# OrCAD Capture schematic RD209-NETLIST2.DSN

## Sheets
1 3: size A3
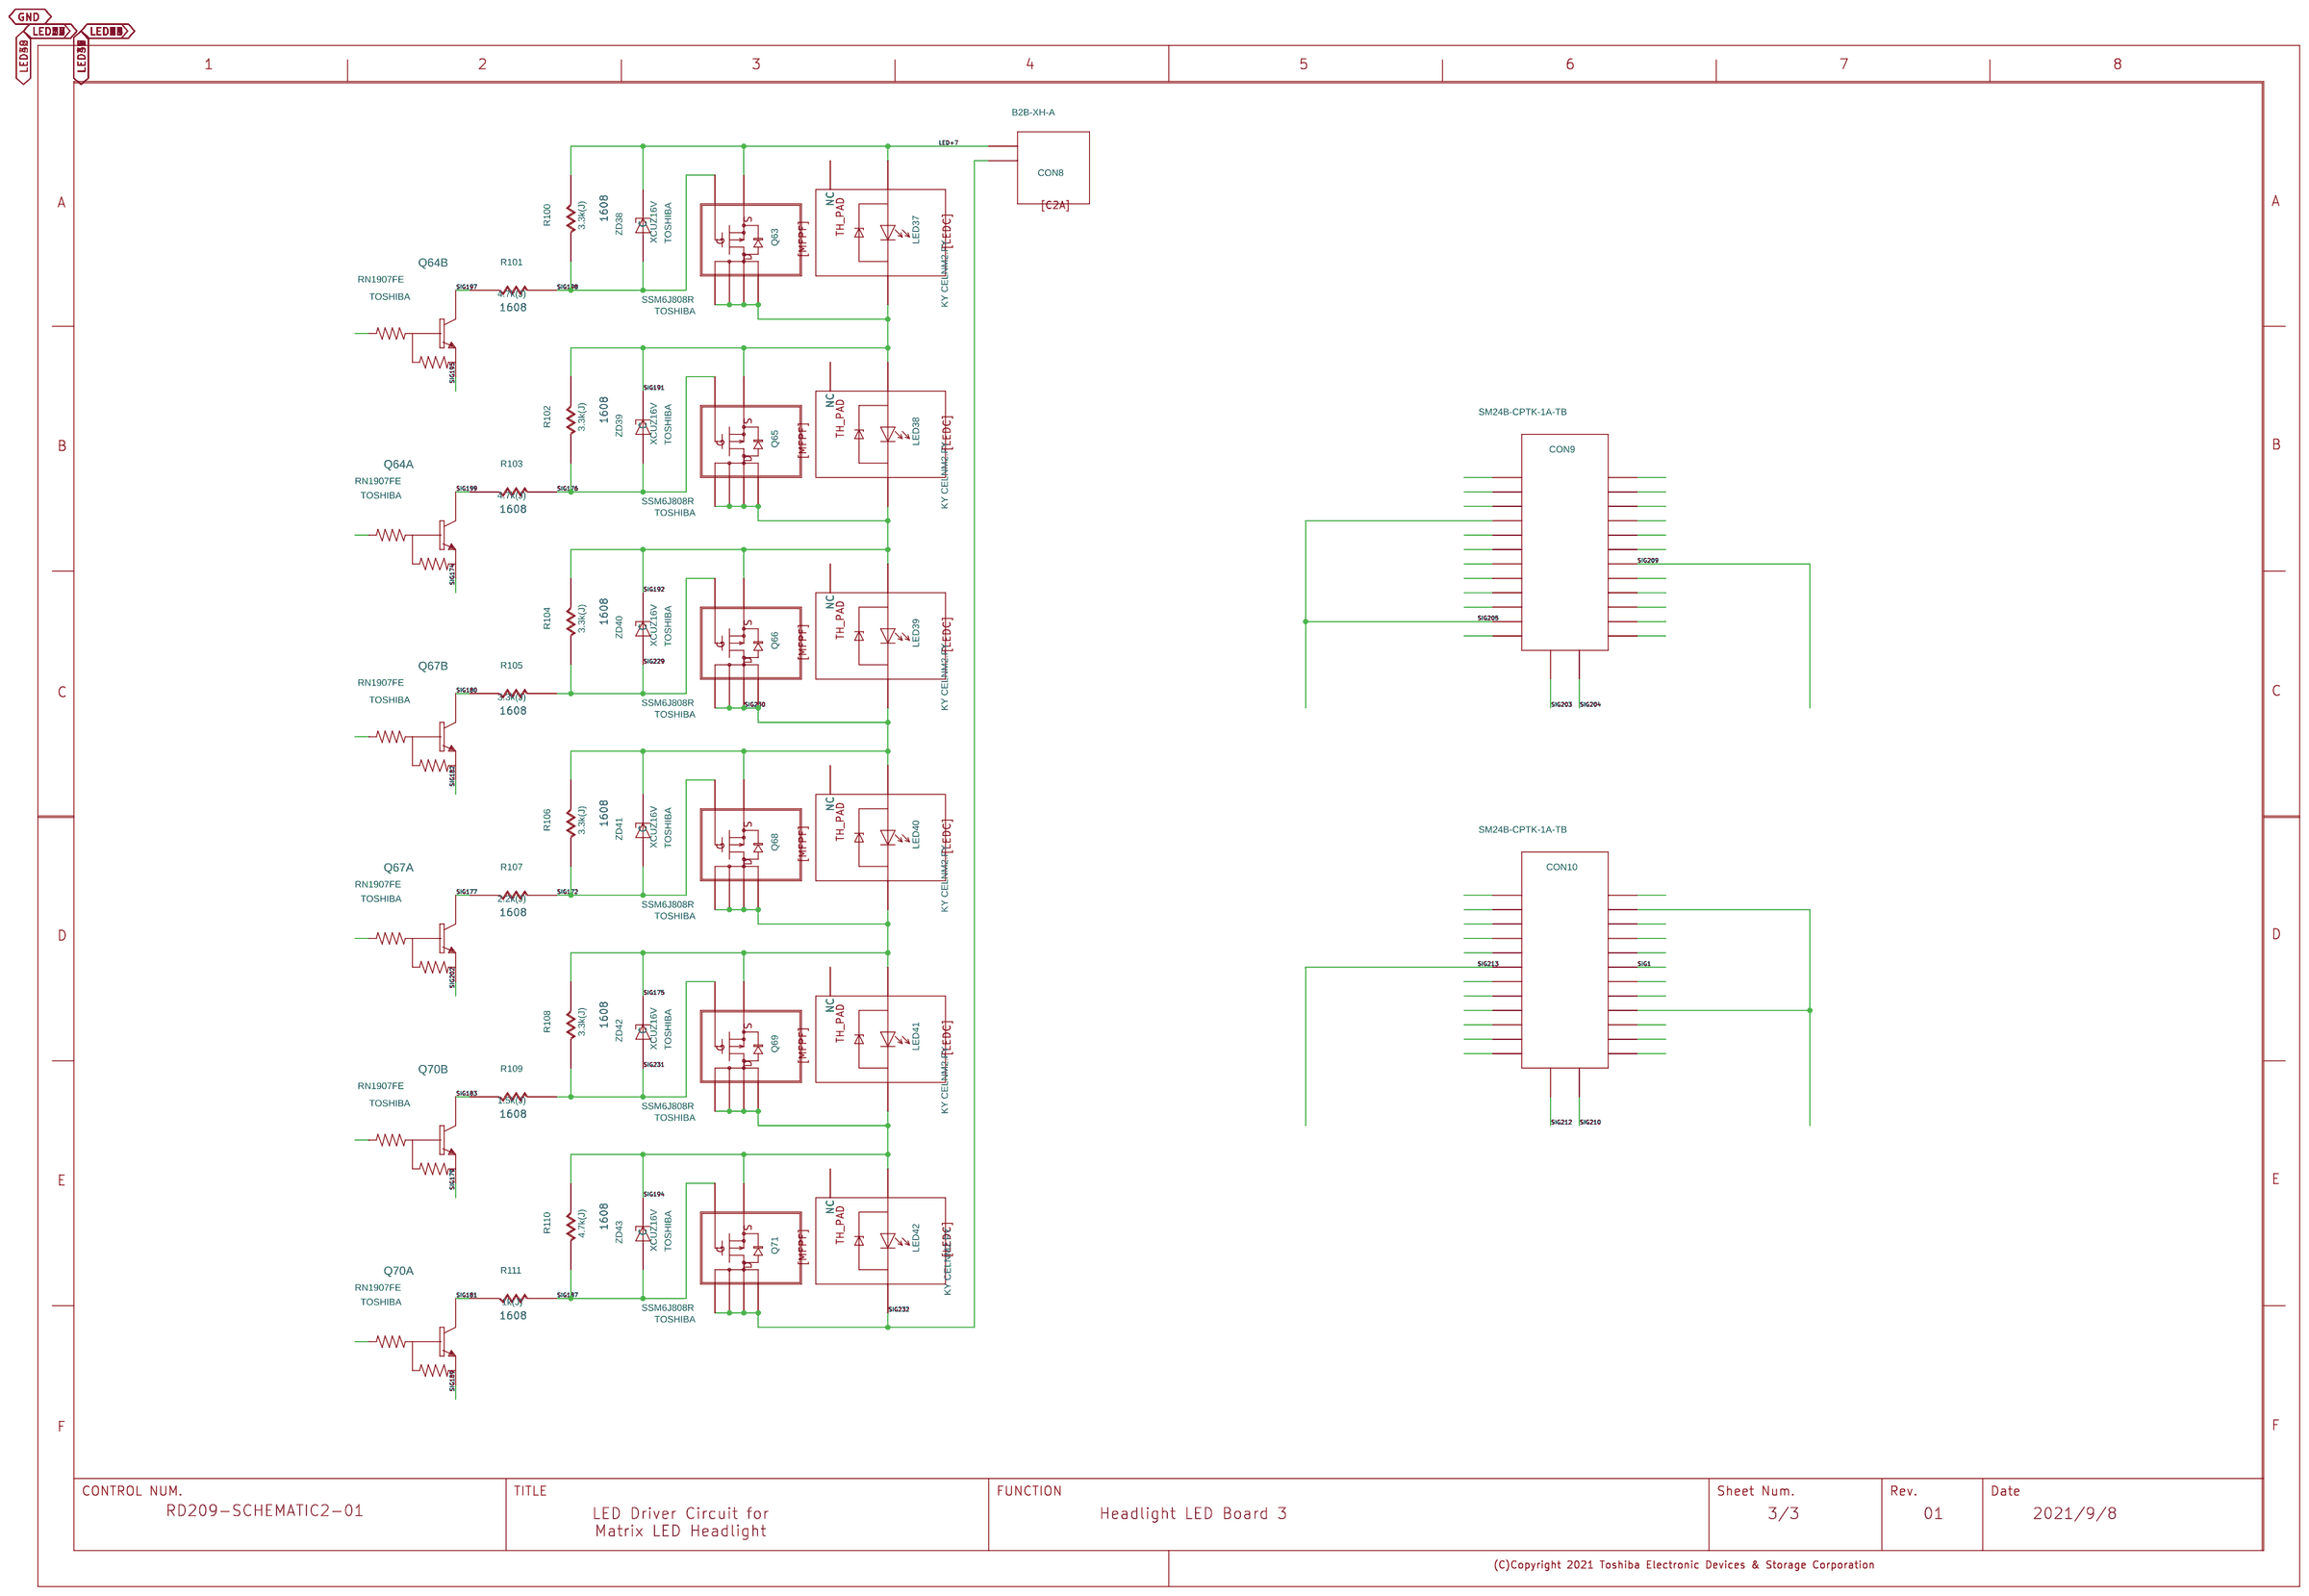
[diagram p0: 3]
2 2: size A3
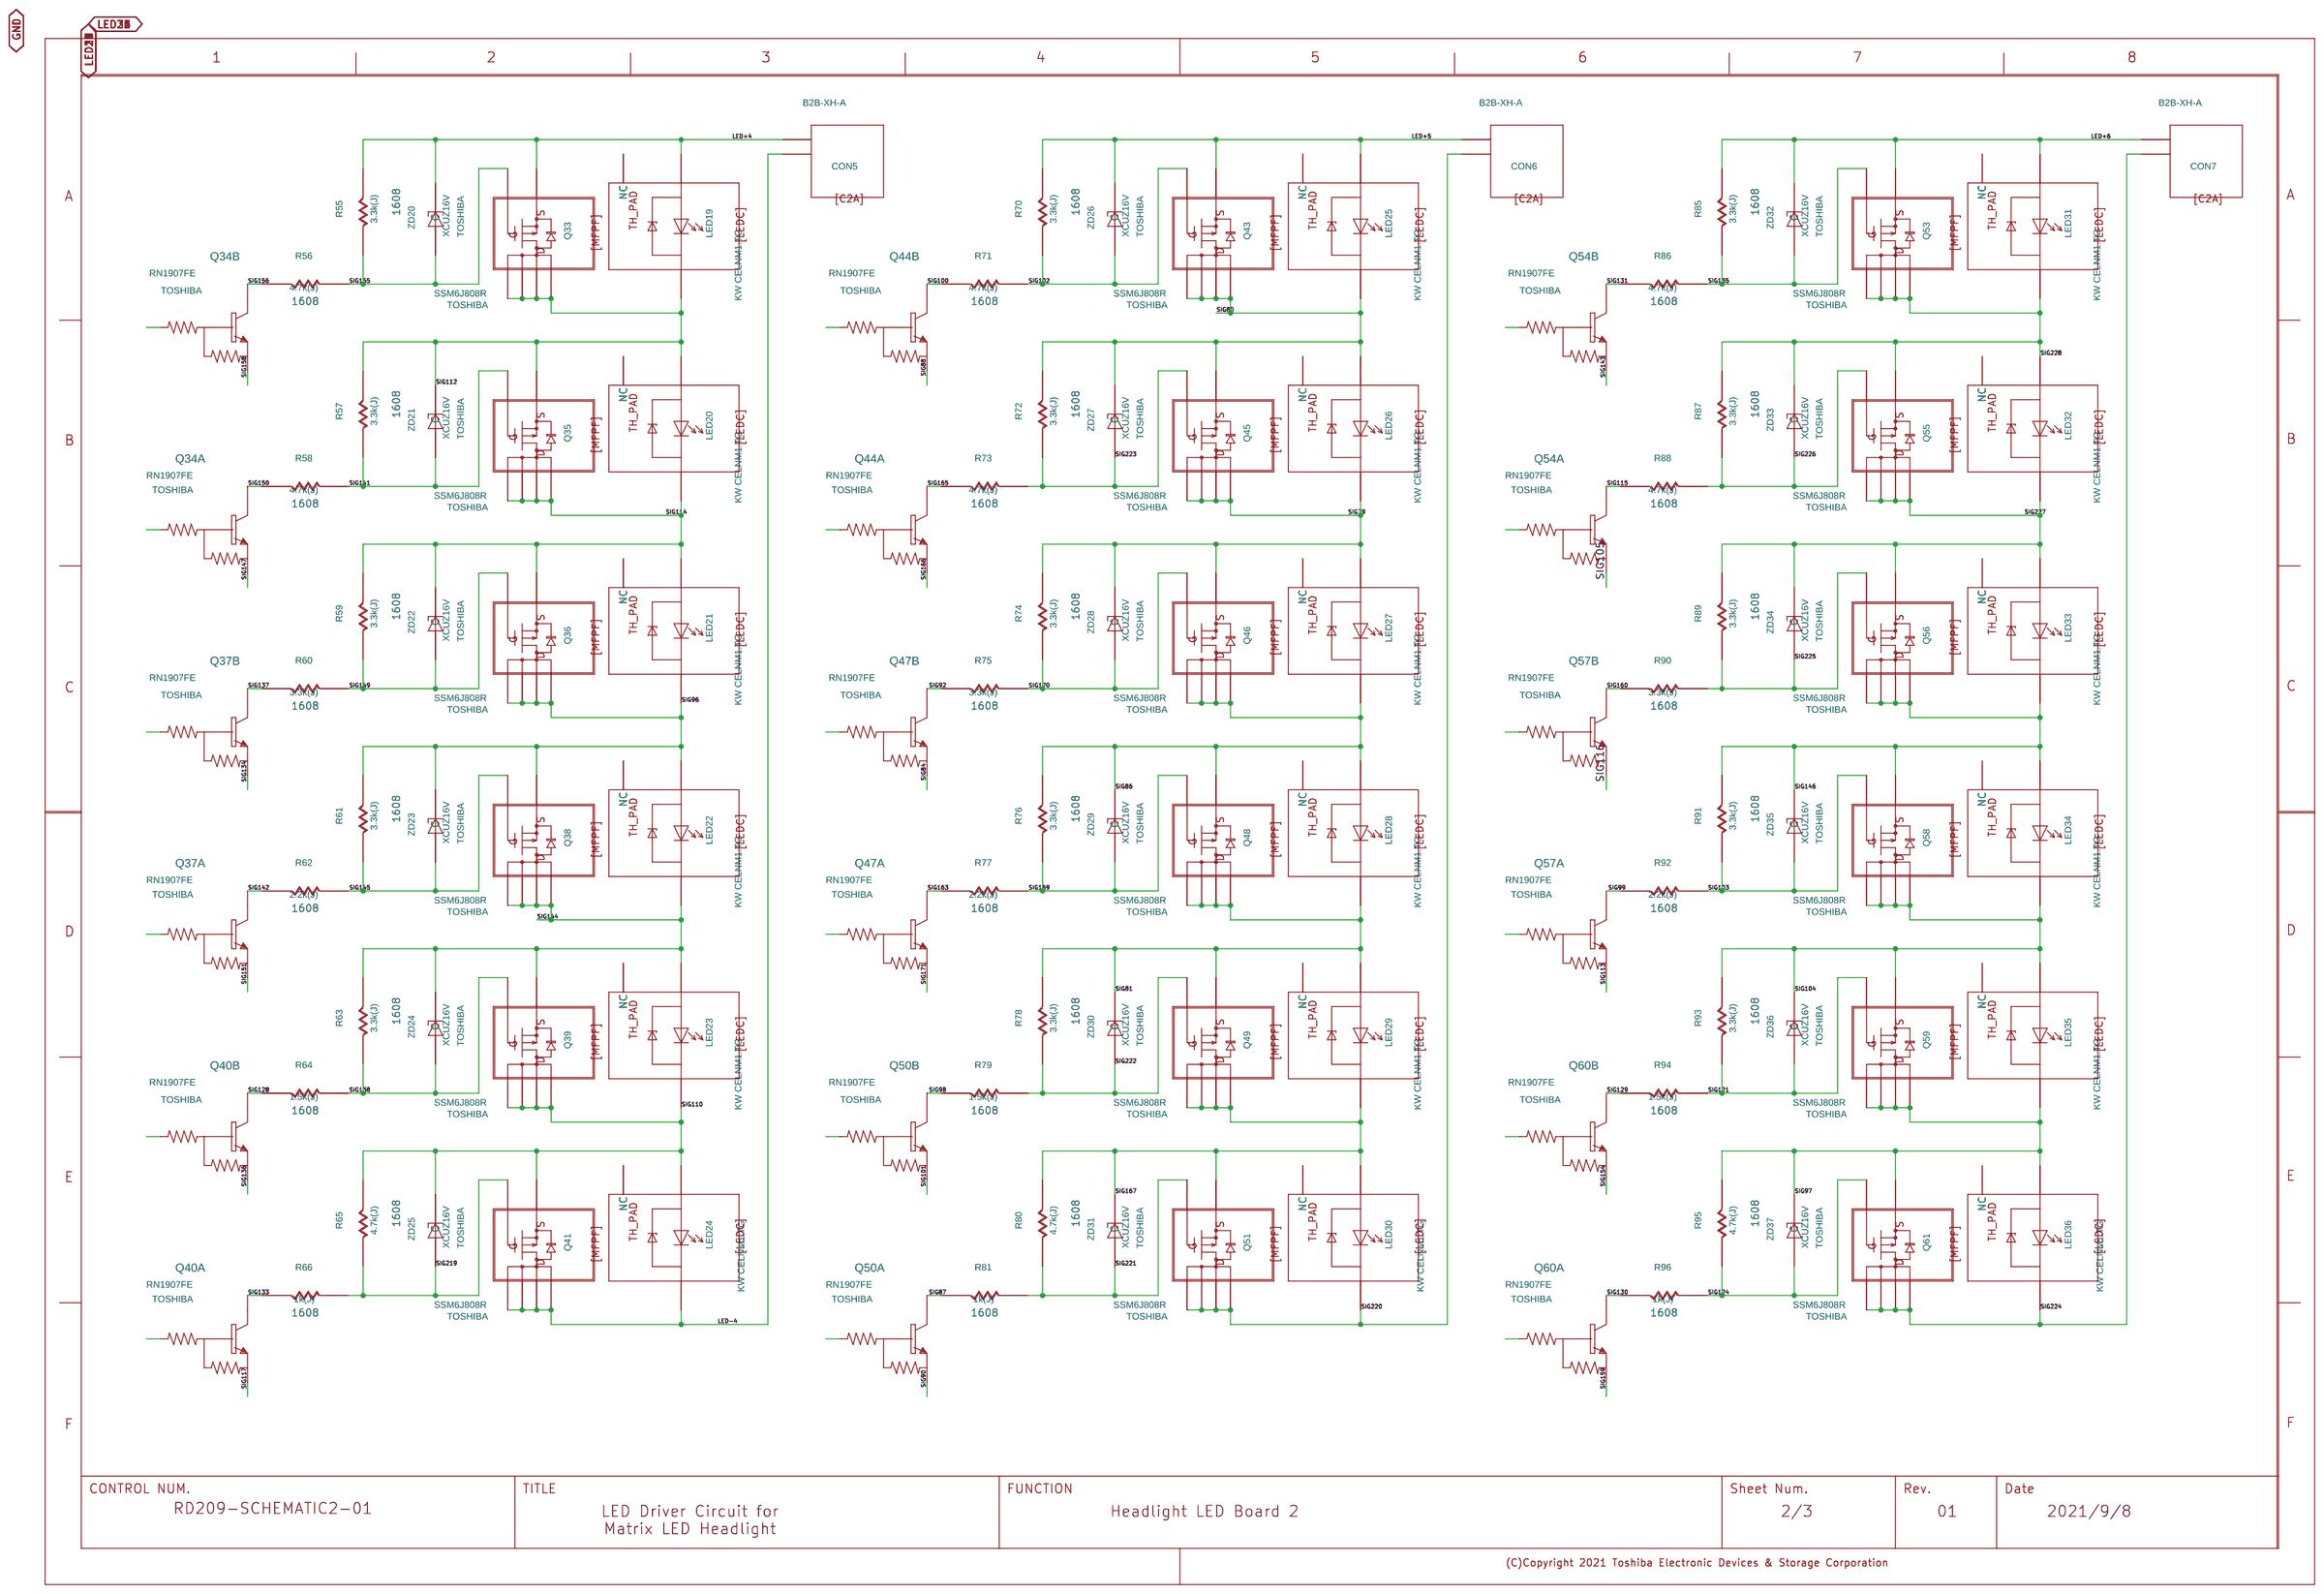
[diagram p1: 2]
3 1: size A3
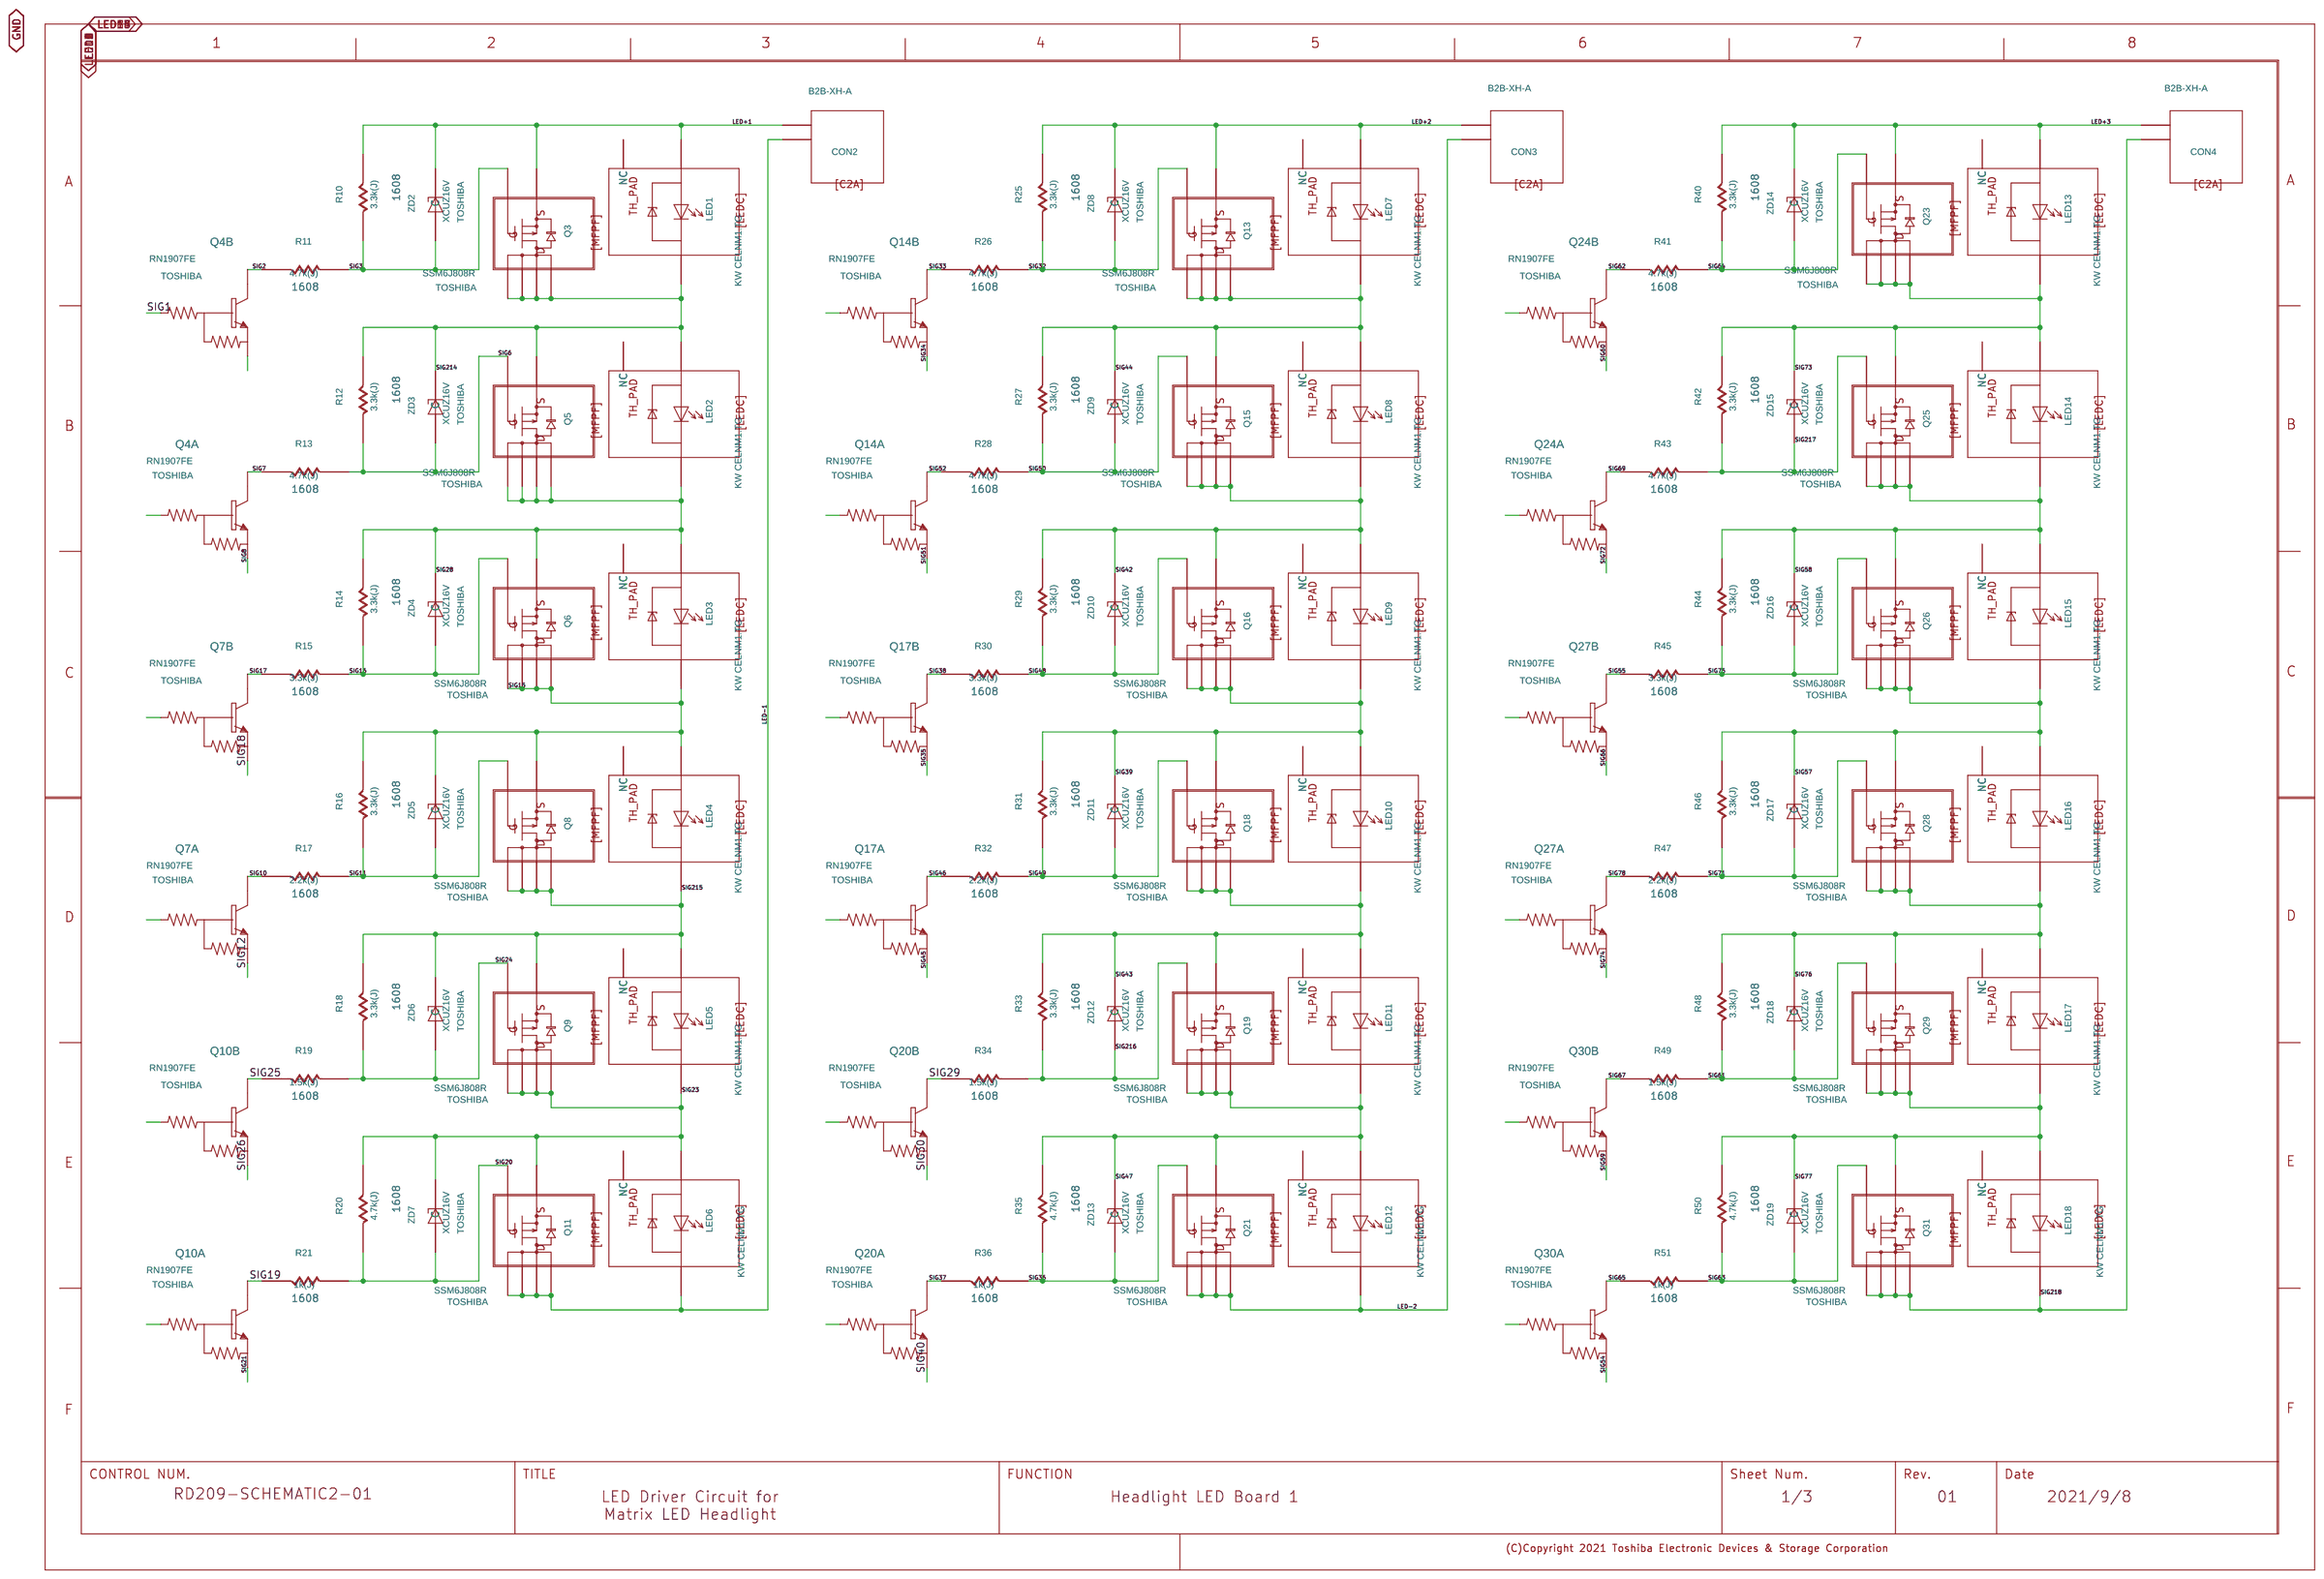
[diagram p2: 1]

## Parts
sheet 1
CON2  C2A
CON3  C2A
CON4  C2A
LED1  LEDC
LED2  LEDC
LED3  LEDC
LED4  LEDC
LED5  LEDC
LED6  LEDC
LED7  LEDC
LED8  LEDC
LED9  LEDC
LED10  LEDC
LED11  LEDC
LED12  LEDC
LED13  LEDC
LED14  LEDC
LED15  LEDC
LED16  LEDC
LED17  LEDC
LED18  LEDC
Q3  MFPF
Q4  RN1907FE_1  (sections A,B)
Q5  MFPF
Q6  MFPF
Q7  RN1907FE_1  (sections A,B)
Q8  MFPF
Q9  MFPF
Q10  RN1907FE_1  (sections A,B)
Q11  MFPF
Q13  MFPF
Q14  RN1907FE_1  (sections A,B)
Q15  MFPF
Q16  MFPF
Q17  RN1907FE_1  (sections A,B)
Q18  MFPF
Q19  MFPF
Q20  RN1907FE_1  (sections A,B)
Q21  MFPF
Q23  MFPF
Q24  RN1907FE_1  (sections A,B)
Q25  MFPF
Q26  MFPF
Q27  RN1907FE_1  (sections A,B)
Q28  MFPF
Q29  MFPF
Q30  RN1907FE_1  (sections A,B)
Q31  MFPF
R10  R
R11  R
R12  R
R13  R
R14  R
R15  R
R16  R
R17  R
R18  R
R19  R
R20  R
R21  R
R25  R
R26  R
R27  R
R28  R
R29  R
R30  R
R31  R
R32  R
R33  R
R34  R
R35  R
R36  R
R40  R
R41  R
R42  R
R43  R
R44  R
R45  R
R46  R
R47  R
R48  R
R49  R
R50  R
R51  R
U?#2  WAKU_DEF100
ZD2  ZD
ZD3  ZD
ZD4  ZD
ZD5  ZD
ZD6  ZD
ZD7  ZD
ZD8  ZD
ZD9  ZD
ZD10  ZD
ZD11  ZD
ZD12  ZD
ZD13  ZD
ZD14  ZD
ZD15  ZD
ZD16  ZD
ZD17  ZD
ZD18  ZD
ZD19  ZD
sheet 2
CON5  C2A
CON6  C2A
CON7  C2A
LED19  LEDC
LED20  LEDC
LED21  LEDC
LED22  LEDC
LED23  LEDC
LED24  LEDC
LED25  LEDC
LED26  LEDC
LED27  LEDC
LED28  LEDC
LED29  LEDC
LED30  LEDC
LED31  LEDC
LED32  LEDC
LED33  LEDC
LED34  LEDC
LED35  LEDC
LED36  LEDC
Q33  MFPF
Q34  RN1907FE_1  (sections A,B)
Q35  MFPF
Q36  MFPF
Q37  RN1907FE_1  (sections A,B)
Q38  MFPF
Q39  MFPF
Q40  RN1907FE_1  (sections A,B)
Q41  MFPF
Q43  MFPF
Q44  RN1907FE_1  (sections A,B)
Q45  MFPF
Q46  MFPF
Q47  RN1907FE_1  (sections A,B)
Q48  MFPF
Q49  MFPF
Q50  RN1907FE_1  (sections A,B)
Q51  MFPF
Q53  MFPF
Q54  RN1907FE_1  (sections A,B)
Q55  MFPF
Q56  MFPF
Q57  RN1907FE_1  (sections A,B)
Q58  MFPF
Q59  MFPF
Q60  RN1907FE_1  (sections A,B)
Q61  MFPF
R55  R
R56  R
R57  R
R58  R
R59  R
R60  R
R61  R
R62  R
R63  R
R64  R
R65  R
R66  R
R70  R
R71  R
R72  R
R73  R
R74  R
R75  R
R76  R
R77  R
R78  R
R79  R
R80  R
R81  R
R85  R
R86  R
R87  R
R88  R
R89  R
R90  R
R91  R
R92  R
R93  R
R94  R
R95  R
R96  R
U?#1  WAKU_DEF100
ZD20  ZD
ZD21  ZD
ZD22  ZD
ZD23  ZD
ZD24  ZD
ZD25  ZD
ZD26  ZD
ZD27  ZD
ZD28  ZD
ZD29  ZD
ZD30  ZD
ZD31  ZD
ZD32  ZD
ZD33  ZD
ZD34  ZD
ZD35  ZD
ZD36  ZD
ZD37  ZD
sheet 3
CON8  C2A
CON9  SM24B_CPTK_1A_TB
CON10  SM24B_CPTK_1A_TB
LED37  LEDC
LED38  LEDC
LED39  LEDC
LED40  LEDC
LED41  LEDC
LED42  LEDC
Q63  MFPF
Q64  RN1907FE_1  (sections A,B)
Q65  MFPF
Q66  MFPF
Q67  RN1907FE_1  (sections A,B)
Q68  MFPF
Q69  MFPF
Q70  RN1907FE_1  (sections A,B)
Q71  MFPF
R100  R
R101  R
R102  R
R103  R
R104  R
R105  R
R106  R
R107  R
R108  R
R109  R
R110  R
R111  R
U?#3  WAKU_DEF100
ZD38  ZD
ZD39  ZD
ZD40  ZD
ZD41  ZD
ZD42  ZD
ZD43  ZD

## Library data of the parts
CON2-CON8 = C2A: CDBNAME: B2B-XH-A; COMP: B2B-XH-A; COMPONENTNAME: B2B-XH-A; COMPONENTTYPE: 4; FUNCN: B2B-XH-A; VAL1: B2B-XH-A; VAL3: B2B-XH-A
LED1-LED36 = LEDC: CDBNAME: KW; COMP: KW; COMPONENTNAME: LED; COMPONENTTYPE: 4; FUNCN: LED; VAL1: KW CELNM1.TG; VAL3: KW CELNM1.TG
Q3 Q5 Q6 Q8 Q9 Q11 Q13 Q15 Q16 Q18 Q19 Q21 Q23 Q25 Q26 Q28 Q29 Q31 Q33 Q35 Q36 Q38 Q39 Q41 Q43 Q45 Q46 Q48 Q49 Q51 Q53 Q55 Q56 Q58 Q59 Q61 Q63 Q65 Q66 Q68 Q69 Q71 = MFPF: CDBNAME: TSOP6F; COMP: TSOP6F; COMPONENTNAME: TSOP6F; COMPONENTTYPE: 4; FUNCN: TSOP6F; USERCOMPTEXT3: TOSHIBA; VAL1: SSM6J808R; VAL3: SSM6J808R
Q4 Q7 Q10 Q14 Q20 Q30 Q34 Q37 Q40 Q44 Q47 Q50 Q54 Q60 Q64 Q67 Q70 = RN1907FE_1: CDBNAME: ES6; COMP: ES6; COMPONENTNAME: ES6; COMPONENTTYPE: 8; CaptureCellPackProp: RN1907FE_1A; FUNCN: ES6; USERCOMPTEXT3: TOSHIBA; VAL1: RN1907FE; VAL3: RN1907FE
Q17 Q24 Q27 Q57 = RN1907FE_1: CDBNAME: ES6; COMP: ES6; COMPONENTNAME: ES6; COMPONENTTYPE: 8; CaptureCellPackProp: RN1907FE_1B; FUNCN: ES6; USERCOMPTEXT3: TOSHIBA; VAL1: RN1907FE; VAL3: RN1907FE
R10 R25 R40 R55 R70 R85 R100 = R: CDBNAME: R0603_1; COMP: R0603_1; COMPONENTNAME: R0603_1; COMPONENTTYPE: 4; FUNCN: R0603_1; VAL1: 3.3k(J); VAL2: 100mW
R11 R26 R41 R56 R71 R86 R101 = R: CDBNAME: R0603_2; COMP: R0603_2; COMPONENTNAME: R0603_2; COMPONENTTYPE: 4; FUNCN: R0603_2; VAL1: 4.7k(J); VAL2: 100mW
R12 R27 R42 R57 R72 R87 R102 = R: CDBNAME: R0603_3; COMP: R0603_3; COMPONENTNAME: R0603_3; COMPONENTTYPE: 4; FUNCN: R0603_3; VAL1: 3.3k(J); VAL2: 100mW
R13 R28 R43 R58 R73 R88 R103 = R: CDBNAME: R0603_4; COMP: R0603_4; COMPONENTNAME: R0603_4; COMPONENTTYPE: 4; FUNCN: R0603_4; VAL1: 4.7k(J); VAL2: 100mW
R14 R29 R44 R59 R74 R89 R104 = R: CDBNAME: R0603_5; COMP: R0603_5; COMPONENTNAME: R0603_5; COMPONENTTYPE: 4; FUNCN: R0603_5; VAL1: 3.3k(J); VAL2: 100mW
R15 R30 R45 R60 R75 R90 R105 = R: CDBNAME: R0603_4; COMP: R0603_4; COMPONENTNAME: R0603_4; COMPONENTTYPE: 4; FUNCN: R0603_4; VAL1: 3.3k(J); VAL2: 100mW
R16 R31 R46 R61 R76 R91 R106 = R: CDBNAME: R0603_6; COMP: R0603_6; COMPONENTNAME: R0603_6; COMPONENTTYPE: 4; FUNCN: R0603_6; VAL1: 3.3k(J); VAL2: 100mW
R17 R32 R47 R62 R77 R92 R107 = R: CDBNAME: R0603_5; COMP: R0603_5; COMPONENTNAME: R0603_5; COMPONENTTYPE: 4; FUNCN: R0603_5; VAL1: 2.2k(J); VAL2: 100mW
R18 R33 R48 R63 R78 R93 R108 = R: CDBNAME: R0603_2; COMP: R0603_2; COMPONENTNAME: R0603_2; COMPONENTTYPE: 4; FUNCN: R0603_2; VAL1: 3.3k(J); VAL2: 100mW
R19 R34 R49 R64 R79 R94 R109 = R: CDBNAME: R0603_1; COMP: R0603_1; COMPONENTNAME: R0603_1; COMPONENTTYPE: 4; FUNCN: R0603_1; VAL1: 1.5k(J); VAL2: 100mW
R20 R35 R50 R65 R80 R95 R110 = R: CDBNAME: R0603_7; COMP: R0603_7; COMPONENTNAME: R0603_7; COMPONENTTYPE: 4; FUNCN: R0603_7; VAL1: 4.7k(J); VAL2: 100mW
R21 R36 R51 R66 R81 R96 R111 = R: CDBNAME: R0603_8; COMP: R0603_8; COMPONENTNAME: R0603_8; COMPONENTTYPE: 4; FUNCN: R0603_8; VAL1: 1k(J); VAL2: 100mW
U?#2 = WAKU_DEF100: COMPONENTTYPE: 2; DATE: 2021/9/8; DRAWINGNUMBER: RD209-SCHEMATIC2-01; FUNCTION: Headlight LED Board 1; REVISION: 01; SHEETNUMBER: 1/3; TITLE: LED Driver Circuit for / Matrix LED Headlight; UPDATEDATE: 2021/09/08; UPDATETIME: 14:28:22
ZD2-ZD43 = ZD: CDBNAME: USC; COMP: USC; COMPONENTNAME: USC; COMPONENTTYPE: 4; FUNCN: USC; USERCOMPTEXT3: TOSHIBA; VAL1: XCUZ16V; VAL3: XCUZ16V
U?#1 = WAKU_DEF100: COMPONENTTYPE: 2; DATE: 2021/9/8; DRAWINGNUMBER: RD209-SCHEMATIC2-01; FUNCTION: Headlight LED Board 2; REVISION: 01; SHEETNUMBER: 2/3; TITLE: LED Driver Circuit for / Matrix LED Headlight; UPDATEDATE: 2021/09/08; UPDATETIME: 14:28:22
CON9 CON10 = SM24B_CPTK_1A_TB: CDBNAME: GAS220000030; COMP: GAS220000030; COMPONENTNAME: GAS220000030; COMPONENTTYPE: 4; FUNCN: GAS220000030; VAL1: SM24B-CPTK-1A-TB; VAL3: SM24B-CPTK-1A-TB
LED37-LED42 = LEDC: CDBNAME: KW; COMP: KW; COMPONENTNAME: LED; COMPONENTTYPE: 4; FUNCN: LED; VAL1: KY CELNM2.FY; VAL3: KY CELNM2.FY
U?#3 = WAKU_DEF100: COMPONENTTYPE: 2; DATE: 2021/9/8; DRAWINGNUMBER: RD209-SCHEMATIC2-01; FUNCTION: Headlight LED Board 3; REVISION: 01; SHEETNUMBER: 3/3; TITLE: LED Driver Circuit for / Matrix LED Headlight; UPDATEDATE: 2021/09/08; UPDATETIME: 14:28:23

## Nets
GND: CON9.1T CON9.2T CON9.4 CON9.11 CON9.19 CON10.1T CON10.2T CON10.6 CON10.14 CON10.21 Q4.1 Q4.4 Q7.1 Q7.4 Q10.1 Q10.4 Q14.1 Q14.4 Q17.1 Q17.4 Q20.1 Q20.4 Q24.1 Q24.4 Q27.1 Q27.4 Q30.1 Q30.4 Q34.1 Q34.4 Q37.1 Q37.4 Q40.1 Q40.4 Q44.1 Q44.4 Q47.1 Q47.4 Q50.1 Q50.4 Q54.1 Q54.4 Q57.1 Q57.4 Q60.1 Q60.4 Q64.1 Q64.4 Q67.1 Q67.4 Q70.1 Q70.4
LED1: CON10.18 Q4.5
LED2: CON10.7 Q4.2
LED3: CON10.19 Q7.5
LED4: CON10.8 Q7.2
LED5: CON10.20 Q10.5
LED6: CON10.9 Q10.2
LED7: CON10.3 Q14.5
LED8: CON10.15 Q14.2
LED9: CON10.4 Q17.5
LED10: CON10.16 Q17.2
LED11: CON10.5 Q20.5
LED12: CON10.17 Q20.2
LED13: CON9.23 Q24.5
LED14: CON9.12 Q24.2
LED15: CON9.24 Q27.5
LED16: CON10.1 Q27.2
LED17: CON10.13 Q30.5
LED18: CON10.2 Q30.2
LED19: CON9.8 Q34.5
LED20: CON9.20 Q34.2
LED21: CON9.9 Q37.5
LED22: CON9.21 Q37.2
LED23: CON9.10 Q40.5
LED24: CON9.22 Q40.2
LED25: CON9.16 Q44.5
LED26: CON9.5 Q44.2
LED27: CON9.17 Q47.5
LED28: CON9.6 Q47.2
LED29: CON9.18 Q50.5
LED30: CON9.7 Q50.2
LED31: CON9.1 Q54.5
LED32: CON9.13 Q54.2
LED33: CON9.2 Q57.5
LED34: CON9.14 Q57.2
LED35: CON9.3 Q60.5
LED36: CON9.15 Q60.2
LED37: CON10.10 Q64.5
LED38: CON10.22 Q64.2
LED39: CON10.11 Q67.5
LED40: CON10.23 Q67.2
LED41: CON10.12 Q70.5
LED42: CON10.24 Q70.2
LED+1: CON2.2 LED1.A Q3.4 R10.2 ZD2.K(C)
LED+2: CON3.2 LED7.A Q13.4 R25.2 ZD8.K(C)
LED+3: CON4.2 LED13.A Q23.4 R40.2 ZD14.K(C)
LED+4: CON5.2 LED19.A Q33.4 R55.2 ZD20.K(C)
LED+5: CON6.2 LED25.A Q43.4 R70.2 ZD26.K(C)
LED+6: CON7.2 LED31.A Q53.4 R85.2 ZD32.K(C)
LED+7: CON8.2 LED37.A Q63.4 R100.2 ZD38.K(C)
LED-1: CON2.1 LED6.C Q11.1 Q11.2 Q11.5 Q11.6
LED-2: CON3.1 LED12.C Q21.1 Q21.2 Q21.5 Q21.6
LED-4: CON5.1 LED24.C Q41.1 Q41.2 Q41.5 Q41.6
SIG2: Q4.3 R11.2
SIG3: Q3.3 R10.1 R11.1 ZD2.A
SIG6: Q5.3 R12.1 R13.1 ZD3.A
SIG7: Q4.6 R13.2
SIG10: Q7.6 R17.2
SIG11: Q8.3 R16.1 R17.1 ZD5.A
SIG15: LED3.C LED4.A Q6.1 Q6.2 Q6.5 Q6.6 Q8.4 R16.2 ZD5.K(C)
SIG16: Q6.3 R14.1 R15.1 ZD4.A
SIG17: Q7.3 R15.2
SIG19: Q10.6 R21.2
SIG20: Q11.3 R20.1 R21.1 ZD7.A
SIG23: LED5.C LED6.A Q9.1 Q9.2 Q9.5 Q9.6 Q11.4 R20.2 ZD7.K(C)
SIG24: Q9.3 R18.1 R19.1 ZD6.A
SIG25: Q10.3 R19.2
SIG28: LED2.C LED3.A Q5.1 Q5.2 Q5.5 Q5.6 Q6.4 R14.2 ZD4.K(C)
SIG29: Q20.3 R34.2
SIG32: Q13.3 R25.1 R26.1 ZD8.A
SIG33: Q14.3 R26.2
SIG36: Q21.3 R35.1 R36.1 ZD13.A
SIG37: Q20.6 R36.2
SIG38: Q17.3 R30.2
SIG39: LED9.C LED10.A Q16.1 Q16.2 Q16.5 Q16.6 Q18.4 R31.2 ZD11.K(C)
SIG42: LED8.C LED9.A Q15.1 Q15.2 Q15.5 Q15.6 Q16.4 R29.2 ZD10.K(C)
SIG43: LED10.C LED11.A Q18.1 Q18.2 Q18.5 Q18.6 Q19.4 R33.2 ZD12.K(C)
SIG44: LED7.C LED8.A Q13.1 Q13.2 Q13.5 Q13.6 Q15.4 R27.2 ZD9.K(C)
SIG46: Q17.6 R32.2
SIG47: LED11.C LED12.A Q19.1 Q19.2 Q19.5 Q19.6 Q21.4 R35.2 ZD13.K(C)
SIG48: Q16.3 R29.1 R30.1 ZD10.A
SIG49: Q18.3 R31.1 R32.1 ZD11.A
SIG50: Q15.3 R27.1 R28.1 ZD9.A
SIG52: Q14.6 R28.2
SIG55: Q27.3 R45.2
SIG57: LED15.C LED16.A Q26.1 Q26.2 Q26.5 Q26.6 Q28.4 R46.2 ZD17.K(C)
SIG58: LED14.C LED15.A Q25.1 Q25.2 Q25.5 Q25.6 Q26.4 R44.2 ZD16.K(C)
SIG61: Q29.3 R48.1 R49.1 ZD18.A
SIG62: Q24.3 R41.2
SIG63: Q31.3 R50.1 R51.1 ZD19.A
SIG64: Q23.3 R40.1 R41.1 ZD14.A
SIG65: Q30.6 R51.2
SIG67: Q30.3 R49.2
SIG69: Q24.6 R43.2
SIG71: Q28.3 R46.1 R47.1 ZD17.A
SIG73: LED13.C LED14.A Q23.1 Q23.2 Q23.5 Q23.6 Q25.4 R42.2 ZD15.K(C)
SIG75: Q26.3 R44.1 R45.1 ZD16.A
SIG76: LED16.C LED17.A Q28.1 Q28.2 Q28.5 Q28.6 Q29.4 R48.2 ZD18.K(C)
SIG77: LED17.C LED18.A Q29.1 Q29.2 Q29.5 Q29.6 Q31.4 R50.2 ZD19.K(C)
SIG78: Q27.6 R47.2
SIG79: LED26.C LED27.A Q45.1 Q45.2 Q45.5 Q45.6 Q46.4 R74.2 ZD28.K(C)
SIG80: LED25.C LED26.A Q43.1 Q43.2 Q43.5 Q43.6 Q45.4 R72.2 ZD27.K(C)
SIG81: LED28.C LED29.A Q48.1 Q48.2 Q48.5 Q48.6 Q49.4 R78.2 ZD30.K(C)
SIG86: LED27.C LED28.A Q46.1 Q46.2 Q46.5 Q46.6 Q48.4 R76.2 ZD29.K(C)
SIG87: Q50.6 R81.2
SIG92: Q47.3 R75.2
SIG96: LED21.C LED22.A Q36.1 Q36.2 Q36.5 Q36.6 Q38.4 R61.2 ZD23.K(C)
SIG97: LED35.C LED36.A Q59.1 Q59.2 Q59.5 Q59.6 Q61.4 R95.2 ZD37.K(C)
SIG98: Q50.3 R79.2
SIG99: Q57.6 R92.2
SIG100: Q44.3 R71.2
SIG102: Q43.3 R70.1 R71.1 ZD26.A
SIG103: Q58.3 R91.1 R92.1 ZD35.A
SIG104: LED34.C LED35.A Q58.1 Q58.2 Q58.5 Q58.6 Q59.4 R93.2 ZD36.K(C)
SIG110: LED23.C LED24.A Q39.1 Q39.2 Q39.5 Q39.6 Q41.4 R65.2 ZD25.K(C)
SIG112: LED19.C LED20.A Q33.1 Q33.2 Q33.5 Q33.6 Q35.4 R57.2 ZD21.K(C)
SIG114: LED20.C LED21.A Q35.1 Q35.2 Q35.5 Q35.6 Q36.4 R59.2 ZD22.K(C)
SIG115: Q54.6 R88.2
SIG121: Q59.3 R93.1 R94.1 ZD36.A
SIG124: Q61.3 R95.1 R96.1 ZD37.A
SIG128: Q40.3 R64.2
SIG129: Q60.3 R94.2
SIG130: Q60.6 R96.2
SIG131: Q54.3 R86.2
SIG133: Q40.6 R66.2
SIG135: Q53.3 R85.1 R86.1 ZD32.A
SIG137: Q37.3 R60.2
SIG138: Q39.3 R63.1 R64.1 ZD24.A
SIG141: Q35.3 R57.1 R58.1 ZD21.A
SIG142: Q37.6 R62.2
SIG144: LED22.C LED23.A Q38.1 Q38.2 Q38.5 Q38.6 Q39.4 R63.2 ZD24.K(C)
SIG145: Q38.3 R61.1 R62.1 ZD23.A
SIG146: LED33.C LED34.A Q56.1 Q56.2 Q56.5 Q56.6 Q58.4 R91.2 ZD35.K(C)
SIG149: Q36.3 R59.1 R60.1 ZD22.A
SIG150: Q34.6 R58.2
SIG155: Q33.3 R55.1 R56.1 ZD20.A
SIG156: Q34.3 R56.2
SIG160: Q57.3 R90.2
SIG163: Q47.6 R77.2
SIG165: Q44.6 R73.2
SIG167: LED29.C LED30.A Q49.1 Q49.2 Q49.5 Q49.6 Q51.4 R80.2 ZD31.K(C)
SIG169: Q48.3 R76.1 R77.1 ZD29.A
SIG170: Q46.3 R74.1 R75.1 ZD28.A
SIG172: Q68.3 R106.1 R107.1 ZD41.A
SIG175: LED40.C LED41.A Q68.1 Q68.2 Q68.5 Q68.6 Q69.4 R108.2 ZD42.K(C)
SIG176: Q65.3 R102.1 R103.1 ZD39.A
SIG177: Q67.6 R107.2
SIG180: Q67.3 R105.2
SIG181: Q70.6 R111.2
SIG183: Q70.3 R109.2
SIG187: Q71.3 R110.1 R111.1 ZD43.A
SIG191: LED37.C LED38.A Q63.1 Q63.2 Q63.5 Q63.6 Q65.4 R102.2 ZD39.K(C)
SIG192: LED38.C LED39.A Q65.1 Q65.2 Q65.5 Q65.6 Q66.4 R104.2 ZD40.K(C)
SIG194: LED41.C LED42.A Q69.1 Q69.2 Q69.5 Q69.6 Q71.4 R110.2 ZD43.K(C)
SIG197: Q64.3 R101.2
SIG198: Q63.3 R100.1 R101.1 ZD38.A
SIG199: Q64.6 R103.2
SIG214: LED1.C LED2.A Q3.1 Q3.2 Q3.5 Q3.6 Q5.4 R12.2 ZD3.K(C)
SIG215: LED4.C LED5.A Q8.1 Q8.2 Q8.5 Q8.6 Q9.4 R18.2 ZD6.K(C)
SIG216: Q19.3 R33.1 R34.1 ZD12.A
SIG217: Q25.3 R42.1 R43.1 ZD15.A
SIG218: CON4.1 LED18.C Q31.1 Q31.2 Q31.5 Q31.6
SIG219: Q41.3 R65.1 R66.1 ZD25.A
SIG220: CON6.1 LED30.C Q51.1 Q51.2 Q51.5 Q51.6
SIG221: Q51.3 R80.1 R81.1 ZD31.A
SIG222: Q49.3 R78.1 R79.1 ZD30.A
SIG223: Q45.3 R72.1 R73.1 ZD27.A
SIG224: CON7.1 LED36.C Q61.1 Q61.2 Q61.5 Q61.6
SIG225: Q56.3 R89.1 R90.1 ZD34.A
SIG226: Q55.3 R87.1 R88.1 ZD33.A
SIG227: LED32.C LED33.A Q55.1 Q55.2 Q55.5 Q55.6 Q56.4 R89.2 ZD34.K(C)
SIG228: LED31.C LED32.A Q53.1 Q53.2 Q53.5 Q53.6 Q55.4 R87.2 ZD33.K(C)
SIG229: Q66.3 R104.1 R105.1 ZD40.A
SIG230: LED39.C LED40.A Q66.1 Q66.2 Q66.5 Q66.6 Q68.4 R106.2 ZD41.K(C)
SIG231: Q69.3 R108.1 R109.1 ZD42.A
SIG232: CON8.1 LED42.C Q71.1 Q71.2 Q71.5 Q71.6

Not connected (* = marked no-connect by the designer): LED1 P_3(NC); LED2 P_3(NC); LED3 P_3(NC); LED4 P_3(NC); LED5 P_3(NC); LED6 P_3(NC); LED7 P_3(NC); LED8 P_3(NC); LED9 P_3(NC); LED10 P_3(NC); LED11 P_3(NC); LED12 P_3(NC); LED13 P_3(NC); LED14 P_3(NC); LED15 P_3(NC); LED16 P_3(NC); LED17 P_3(NC); LED18 P_3(NC); LED19 P_3(NC); LED20 P_3(NC); LED21 P_3(NC); LED22 P_3(NC); LED23 P_3(NC); LED24 P_3(NC); LED25 P_3(NC); LED26 P_3(NC); LED27 P_3(NC); LED28 P_3(NC); LED29 P_3(NC); LED30 P_3(NC); LED31 P_3(NC); LED32 P_3(NC); LED33 P_3(NC); LED34 P_3(NC); LED35 P_3(NC); LED36 P_3(NC); LED37 P_3(NC); LED38 P_3(NC); LED39 P_3(NC); LED40 P_3(NC); LED41 P_3(NC); LED42 P_3(NC)

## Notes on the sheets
sheet 1
- 1608
- 1608
- 1608
- 1608
- 1608
- 1608
- 1608
- 1608
- 1608
- 1608
- 1608
- 1608
sheet 2
- 1608
- 1608
- 1608
- 1608
- 1608
- 1608
- 1608
- 1608
- 1608
- 1608
- 1608
- 1608
- 1608
- 1608
- 1608
- 1608
- 1608
- 1608
- 1608
- 1608
- 1608
- 1608
- 1608
- 1608
- 1608
- 1608
- 1608
- 1608
- 1608
- 1608
- 1608
- 1608
- 1608
- 1608
- 1608
- 1608
sheet 3
- 1608
- 1608
- 1608
- 1608
- 1608
- 1608
- 1608
- 1608
- 1608
- 1608
- 1608
- 1608
- 1608
- 1608
- 1608
- 1608
- 1608
- 1608
- 1608
- 1608
- 1608
- 1608
- 1608
- 1608
- 1608
- 1608
- 1608
- 1608
- 1608
- 1608
- 1608
- 1608
- 1608
- 1608
- 1608
- 1608
